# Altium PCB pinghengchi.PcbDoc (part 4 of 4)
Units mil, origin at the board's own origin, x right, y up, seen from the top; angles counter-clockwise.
Board outline 3880 x 3935 mil, 2 copper layers (Top Layer, Bottom Layer); 79 components, 147 nets, 520 pads, 52 vias.
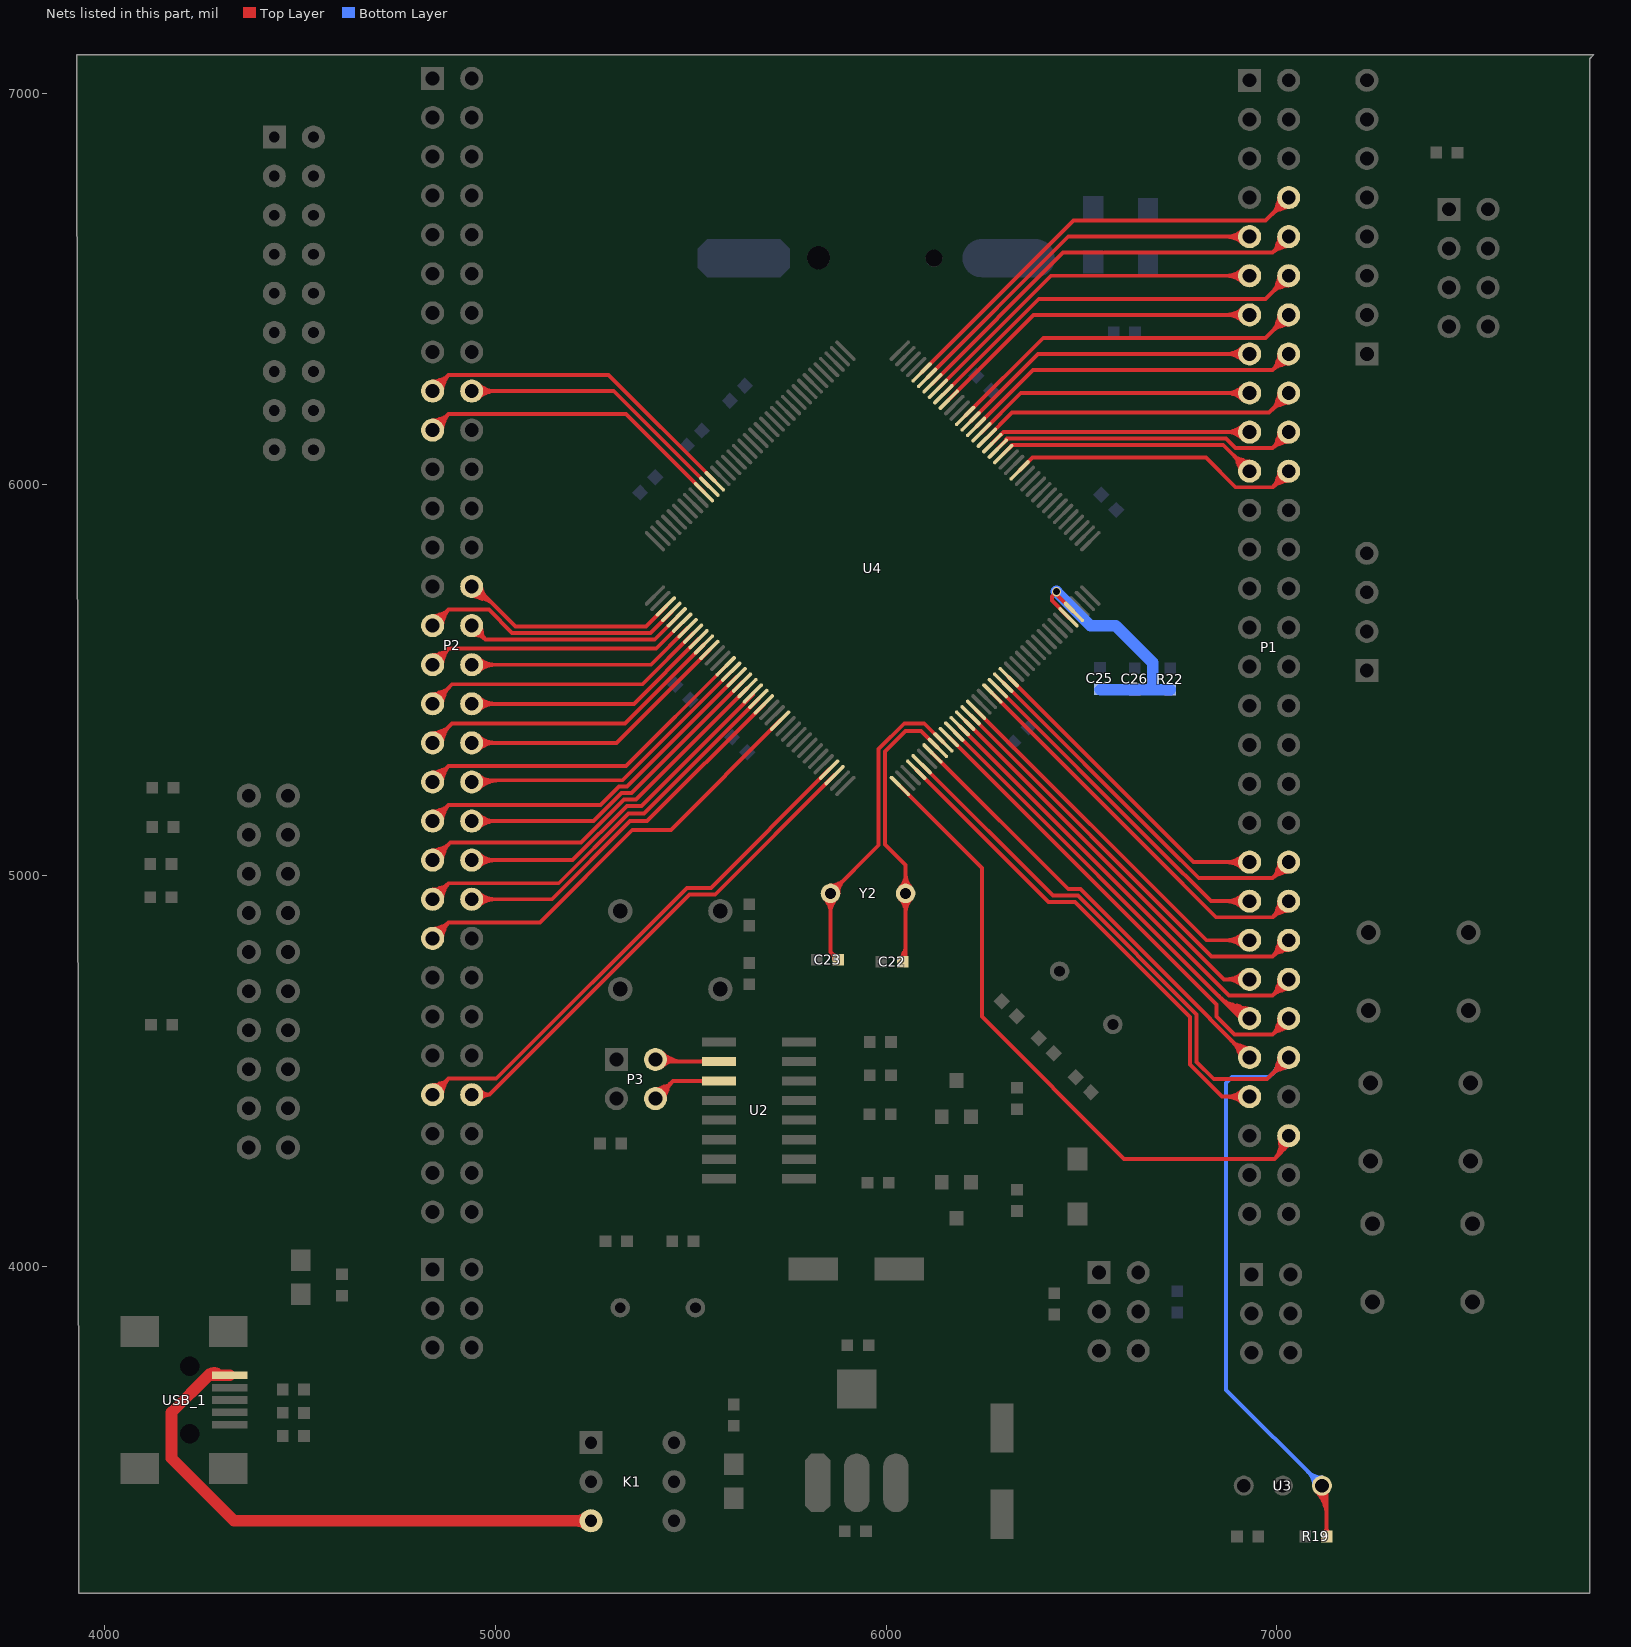
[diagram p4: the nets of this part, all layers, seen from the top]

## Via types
v1: diameter 24, hole 18, Top Layer to Bottom Layer, 42 vias
v2: diameter 24, hole 16, Top Layer to Bottom Layer, 4 vias
v3: diameter 125.98, hole 118.11, Top Layer to Bottom Layer, 4 vias
v4: diameter 30, hole 20, Top Layer to Bottom Layer, 2 vias

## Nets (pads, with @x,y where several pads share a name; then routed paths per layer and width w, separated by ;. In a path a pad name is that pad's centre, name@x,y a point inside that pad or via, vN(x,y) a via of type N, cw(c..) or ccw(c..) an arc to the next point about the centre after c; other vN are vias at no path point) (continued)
PC7: P2.17 U4.97 | length 1224.5
  Top Layer w10: P2.17@4834.67,6241.26 cw(c4872.93,6232.2) 4863.31,6270.32 ; P2.17@4840,6240 4881.03,6281.03 ; P2.17@4841.26,6234.67 ccw(c4832.2,6272.93) 4870.32,6263.31 ; U4.97@5561.97,6009.22 5290.17,6281.03 4881.03,6281.03 ; 4864.3,6264.3 ccw(c4887.9,6240.7) 4854.53,6240.21 cw(c4887.9,6240.7) 4864.3,6264.3 ; 4864.3,6264.3 cw(c4840.7,6287.9) 4840.21,6254.53 ccw(c4840.7,6287.9) 4864.3,6264.3 ; 4881.03,6281.03 ccw(c4920.87,6241.18) 4864.52,6240.36 cw(c4920.87,6241.18) 4881.03,6281.03 ; 4881.03,6281.03 cw(c4841.18,6320.87) 4840.36,6264.52 ccw(c4841.18,6320.87) 4881.03,6281.03
PC8: P2.18 U4.98 | length 1005.6
  Top Layer w10: P2.18@4940,6240 5303.35,6240 U4.98@5548.05,5995.3 ; 4975.07,6240 ccw(c4975.07,6204.93) 4950.27,6229.73 cw(c4975.07,6204.93) 4975.07,6240 ; 4975.07,6240 cw(c4975.07,6275.07) 4950.27,6250.27 ccw(c4975.07,6275.07) 4975.07,6240 ; 4999.21,6240 ccw(c4999.21,6180.79) 4957.34,6222.66 cw(c4999.21,6180.79) 4999.21,6240 ; 4999.21,6240 cw(c4999.21,6299.21) 4957.34,6257.34 ccw(c4999.21,6299.21) 4999.21,6240
PC9: P2.19 U4.99 | length 1166.7
  Top Layer w10: P2.19@4834.67,6141.26 cw(c4872.93,6132.2) 4863.31,6170.32 ; P2.19@4840,6140 4881.03,6181.03 ; P2.19@4841.26,6134.67 ccw(c4832.2,6172.93) 4870.32,6163.31 ; U4.99@5534.14,5981.38 5334.49,6181.03 4881.03,6181.03 ; 4864.3,6164.3 ccw(c4887.9,6140.7) 4854.53,6140.21 cw(c4887.9,6140.7) 4864.3,6164.3 ; 4864.3,6164.3 cw(c4840.7,6187.9) 4840.21,6154.53 ccw(c4840.7,6187.9) 4864.3,6164.3 ; 4881.03,6181.03 ccw(c4920.87,6141.18) 4864.52,6140.36 cw(c4920.87,6141.18) 4881.03,6181.03 ; 4881.03,6181.03 cw(c4841.18,6220.87) 4840.36,6164.52 ccw(c4841.18,6220.87) 4881.03,6181.03
PC10: P2.28 U4.111 | length 1013.3
  Top Layer w10: P2.28@4934.82,5738.23 ccw(c4978.99,5753.36) 4966.91,5708.26 ; P2.28@4940,5740 4950,5740 5052,5638 5385.63,5638 U4.111@5436.7,5689.07 ; P2.28@4940.22,5745.47 cw(c4938.95,5714.08) 4969.29,5722.21 ; P2.28@4944.28,5741.47 ccw(c5000.4,5760.7) 4985.04,5703.4 ; P2.28@4944.48,5740.66 ccw(c4970.46,5744.5) 4963.67,5719.13 ; P2.28@4940,5715.47 cw(c4940,5632.12) 4998.94,5691.06 ccw(c4940,5632.12) P2.28@4940,5715.47 ; P2.28@4940,5725.47 cw(c4940,5666.26) 4981.87,5708.13 ccw(c4940,5666.26) P2.28@4940,5725.47 ; P2.28@4964.53,5740 ccw(c4999.6,5740) 4974.8,5715.2 cw(c4999.6,5740) P2.28@4964.53,5740
PC11: P2.29 U4.112 | length 1047.4
  Top Layer w10: P2.29@4834.67,5641.26 cw(c4872.93,5632.2) 4863.31,5670.32 ; P2.29@4840,5640 4881.03,5681.03 ; P2.29@4841.26,5634.67 ccw(c4832.2,5672.93) 4870.32,5663.31 ; U4.112@5450.62,5675.15 5396.96,5621.5 5043.5,5621.5 4983.97,5681.03 4881.03,5681.03 ; 4864.3,5664.3 ccw(c4887.9,5640.7) 4854.53,5640.21 cw(c4887.9,5640.7) 4864.3,5664.3 ; 4864.3,5664.3 cw(c4840.7,5687.9) 4840.21,5654.53 ccw(c4840.7,5687.9) 4864.3,5664.3 ; 4881.03,5681.03 ccw(c4920.87,5641.18) 4864.52,5640.36 cw(c4920.87,5641.18) 4881.03,5681.03 ; 4881.03,5681.03 cw(c4841.18,5720.87) 4840.36,5664.52 ccw(c4841.18,5720.87) 4881.03,5681.03
PC12: P2.30 U4.113 | length 769.4
  Top Layer w10: P2.30@4927.76,5630.53 ccw(c4962.2,5657.17) 4956.68,5613.99 ; P2.30@4940,5640 4975,5605 ; P2.30@4949.47,5652.24 cw(c4922.83,5617.8) 4966.01,5623.32 ; U4.113@5464.54,5661.23 5408.3,5605 4975,5605 ; 4975,5605 ccw(c4948.36,5578.36) 4943.3,5615.69 cw(c4948.36,5578.36) 4975,5605 ; 4975,5605 cw(c5001.64,5631.64) 4964.31,5636.7 ccw(c5001.64,5631.64) 4975,5605
PC13: P1.51 U4.7 | length 1473.5
  Top Layer w10: U4.7@6118.75,5313.25 6466,4966 6497.34,4966 6828.5,4634.84 6828.5,4633.17 6926.67,4535 P1.51@6930,4535 ; 6899.89,4555.83 ccw(c6934.63,4565.13) P1.51@6929.17,4529.59 ; 6906.13,4565.92 cw(c6895.51,4526.27) P1.51@6935.31,4536.34 ; 6882.44,4579.23 ccw(c6930,4626.79) 6930,4559.53 cw(c6930,4626.79) 6882.44,4579.23 ; 6890.49,4571.18 cw(c6854.31,4535) 6905.47,4535 ccw(c6854.31,4535) 6890.49,4571.18 ; 6899.51,4562.16 ccw(c6930,4592.65) 6930,4549.53 cw(c6930,4592.65) 6899.51,4562.16
PC14: C22.2 U4.8 Y2.1 | length 1177.4
  Top Layer w10: 6045.52,4804.48 ccw(c6056.78,4797.97) C22.2@6048.71,4787.78 ; U4.8@6132.67,5327.17 6089.84,5370 6049.77,5370 5997.59,5317.83 5997.59,5080.41 6050,5028 Y2.1@6050,4955 6050,4787.44 C22.2@6042.5,4779.94 ; C22.2@6042.5,4779.94 ccw(c6024.39,4798.04) 6050,4798.04 cw(c6024.39,4798.04) C22.2@6042.5,4779.94 ; 6050,4906.72 ccw(c6001.72,4906.72) 6035.86,4940.86 cw(c6001.72,4906.72) 6050,4906.72 ; 6050,4906.72 cw(c6098.28,4906.72) 6064.14,4940.86 ccw(c6098.28,4906.72) 6050,4906.72 ; 6050,5003.28 ccw(c6098.28,5003.28) 6064.14,4969.14 cw(c6098.28,5003.28) 6050,5003.28 ; 6050,5003.28 cw(c6001.72,5003.28) 6035.86,4969.14 ccw(c6001.72,5003.28) 6050,5003.28 ; C22.2@6035.43,4787.01 ccw(c6000.25,4822.18) 6050,4822.18 cw(c6000.25,4822.18) C22.2@6035.43,4787.01
PC15: C23.2 U4.9 Y2.2 | length 1268.3
  Top Layer w10: C23.2@5877.5,4784.94 5857.87,4804.56 Y2.2@5857.87,4955 ; 5883.07,4981.75 ccw(c5892.12,4947.99) Y2.2@5857.87,4955 ; 5884.63,4980.2 cw(c5850.86,4989.24) Y2.2@5857.87,4955 ; U4.9@6146.59,5341.09 6097.68,5390 6046.43,5390 5981.09,5324.66 5981.09,5078.22 Y2.2@5857.87,4955 ; 5857.87,4906.72 ccw(c5809.59,4906.72) 5843.73,4940.86 cw(c5809.59,4906.72) 5857.87,4906.72 ; 5857.87,4906.72 cw(c5906.16,4906.72) 5872.02,4940.86 ccw(c5906.16,4906.72) 5857.87,4906.72 ; 5860.43,4802.01 ccw(c5877.5,4819.08) 5877.5,4794.94 cw(c5877.5,4819.08) 5860.43,4802.01 ; 5860.43,4802.01 cw(c5843.36,4784.94) 5867.5,4784.94 ccw(c5843.36,4784.94) 5860.43,4802.01 ; 5892.02,4989.14 ccw(c5926.16,4955) 5877.87,4955 cw(c5926.16,4955) 5892.02,4989.14 ; 5892.02,4989.14 cw(c5857.87,5023.28) 5857.87,4975 ccw(c5857.87,5023.28) 5892.02,4989.14
PD0: P2.31 U4.114 | length 1055.8
  Top Layer w10: P2.31@4834.67,5541.26 cw(c4872.93,5532.2) 4863.31,5570.32 ; P2.31@4840,5540 4881.03,5581.03 ; P2.31@4841.26,5534.67 ccw(c4832.2,5572.93) 4870.32,5563.31 ; U4.114@5478.46,5647.31 5412.17,5581.03 4881.03,5581.03 ; 4864.3,5564.3 ccw(c4887.9,5540.7) 4854.53,5540.21 cw(c4887.9,5540.7) 4864.3,5564.3 ; 4864.3,5564.3 cw(c4840.7,5587.9) 4840.21,5554.53 ccw(c4840.7,5587.9) 4864.3,5564.3 ; 4881.03,5581.03 ccw(c4920.87,5541.18) 4864.52,5540.36 cw(c4920.87,5541.18) 4881.03,5581.03 ; 4881.03,5581.03 cw(c4841.18,5620.87) 4840.36,5564.52 ccw(c4841.18,5620.87) 4881.03,5581.03
PD1: P2.32 U4.115 | length 887.3
  Top Layer w10: P2.32@4940,5540 5398.98,5540 U4.115@5492.38,5633.4 ; 4975.07,5540 ccw(c4975.07,5504.93) 4950.27,5529.73 cw(c4975.07,5504.93) 4975.07,5540 ; 4975.07,5540 cw(c4975.07,5575.07) 4950.27,5550.27 ccw(c4975.07,5575.07) 4975.07,5540 ; 4999.21,5540 ccw(c4999.21,5480.79) 4957.34,5522.66 cw(c4999.21,5480.79) 4999.21,5540 ; 4999.21,5540 cw(c4999.21,5599.21) 4957.34,5557.34 ccw(c4999.21,5599.21) 4999.21,5540
PD2: P2.33 U4.116 | length 1122
  Top Layer w10: P2.33@4834.64,5441.1 cw(c4872.3,5433.39) 4862.35,5470.52 ; P2.33@4840,5440 4890,5490 5376.82,5490 U4.116@5506.3,5619.48 ; P2.33@4841.1,5434.64 ccw(c4833.39,5472.3) 4870.52,5462.35 ; 4864.8,5464.8 ccw(c4889.6,5440) 4854.53,5440 cw(c4889.6,5440) 4864.8,5464.8 ; 4864.8,5464.8 cw(c4840,5489.6) 4840,5454.53 ccw(c4840,5489.6) 4864.8,5464.8 ; 4881.87,5481.87 ccw(c4923.74,5440) 4864.53,5440 cw(c4923.74,5440) 4881.87,5481.87 ; 4881.87,5481.87 cw(c4840,5523.74) 4840,5464.53 ccw(c4840,5523.74) 4881.87,5481.87
PD3: P2.34 U4.117 | length 945
  Top Layer w10: P2.34@4940,5440 5354.66,5440 U4.117@5520.22,5605.56 ; 4975.07,5440 ccw(c4975.07,5404.93) 4950.27,5429.73 cw(c4975.07,5404.93) 4975.07,5440 ; 4975.07,5440 cw(c4975.07,5475.07) 4950.27,5450.27 ccw(c4975.07,5475.07) 4975.07,5440 ; 4999.21,5440 ccw(c4999.21,5380.79) 4957.34,5422.66 cw(c4999.21,5380.79) 4999.21,5440 ; 4999.21,5440 cw(c4999.21,5499.21) 4957.34,5457.34 ccw(c4999.21,5499.21) 4999.21,5440
PD4: P2.35 U4.118 | length 1179.7
  Top Layer w10: P2.35@4834.64,5341.1 cw(c4872.3,5333.39) 4862.35,5370.52 ; P2.35@4840,5340 4890,5390 5332.5,5390 U4.118@5534.14,5591.64 ; P2.35@4841.1,5334.64 ccw(c4833.39,5372.3) 4870.52,5362.35 ; 4864.8,5364.8 ccw(c4889.6,5340) 4854.53,5340 cw(c4889.6,5340) 4864.8,5364.8 ; 4864.8,5364.8 cw(c4840,5389.6) 4840,5354.53 ccw(c4840,5389.6) 4864.8,5364.8 ; 4881.87,5381.87 ccw(c4923.74,5340) 4864.53,5340 cw(c4923.74,5340) 4881.87,5381.87 ; 4881.87,5381.87 cw(c4840,5423.74) 4840,5364.53 ccw(c4840,5423.74) 4881.87,5381.87
PD5: P2.36 U4.119 | length 1002.7
  Top Layer w10: P2.36@4940,5340 5310.34,5340 U4.119@5548.05,5577.72 ; 4975.07,5340 ccw(c4975.07,5304.93) 4950.27,5329.73 cw(c4975.07,5304.93) 4975.07,5340 ; 4975.07,5340 cw(c4975.07,5375.07) 4950.27,5350.27 ccw(c4975.07,5375.07) 4975.07,5340 ; 4999.21,5340 ccw(c4999.21,5280.79) 4957.34,5322.66 cw(c4999.21,5280.79) 4999.21,5340 ; 4999.21,5340 cw(c4999.21,5399.21) 4957.34,5357.34 ccw(c4999.21,5399.21) 4999.21,5340
PD6: P2.37 U4.122 | length 1245.3
  Top Layer w10: P2.37@4834.67,5241.26 cw(c4872.93,5232.2) 4863.31,5270.32 ; P2.37@4840,5240 4881.03,5281.03 ; P2.37@4841.26,5234.67 ccw(c4832.2,5272.93) 4870.32,5263.31 ; U4.122@5589.81,5535.96 5334.88,5281.03 4881.03,5281.03 ; 4864.3,5264.3 ccw(c4887.9,5240.7) 4854.53,5240.21 cw(c4887.9,5240.7) 4864.3,5264.3 ; 4864.3,5264.3 cw(c4840.7,5287.9) 4840.21,5254.53 ccw(c4840.7,5287.9) 4864.3,5264.3 ; 4881.03,5281.03 ccw(c4920.87,5241.18) 4864.52,5240.36 cw(c4920.87,5241.18) 4881.03,5281.03 ; 4881.03,5281.03 cw(c4841.18,5320.87) 4840.36,5264.52 ccw(c4841.18,5320.87) 4881.03,5281.03
PD7: P2.38 U4.123 | length 1045.8
  Top Layer w10: P2.38@4940,5240 4944.5,5244.5 5326.19,5244.5 U4.123@5603.73,5522.04 ; P2.38@4950.27,5229.73 cw(c4985.94,5194.06) 4985.94,5244.5 ccw(c4985.94,5194.06) P2.38@4950.27,5229.73 ; P2.38@4957.34,5222.66 cw(c5010.08,5169.92) 5010.08,5244.5 ccw(c5010.08,5169.92) P2.38@4957.34,5222.66 ; P2.38@4957.34,5257.34 ccw(c4988.35,5288.35) 4988.35,5244.5 cw(c4988.35,5288.35) P2.38@4957.34,5257.34
PE0: P2.53 U4.141 | length 1731.6
  Top Layer w10: P2.53@4834.67,4441.26 cw(c4872.93,4432.2) 4863.31,4470.32 ; P2.53@4840,4440 4881.03,4481.03 ; P2.53@4841.26,4434.67 ccw(c4832.2,4472.93) 4870.32,4463.31 ; U4.141@5854.28,5271.49 5551.79,4969 5490.67,4969 5002.69,4481.03 4881.03,4481.03 ; 4864.3,4464.3 ccw(c4887.9,4440.7) 4854.53,4440.21 cw(c4887.9,4440.7) 4864.3,4464.3 ; 4864.3,4464.3 cw(c4840.7,4487.9) 4840.21,4454.53 ccw(c4840.7,4487.9) 4864.3,4464.3 ; 4881.03,4481.03 ccw(c4920.87,4441.18) 4864.52,4440.36 cw(c4920.87,4441.18) 4881.03,4481.03 ; 4881.03,4481.03 cw(c4841.18,4520.87) 4840.36,4464.52 ccw(c4841.18,4520.87) 4881.03,4481.03
PE1: P2.54 U4.142 | length 1382.7
  Top Layer w10: P2.54@4940,4440 4985,4440 ; U4.142@5868.2,5257.57 5563.13,4952.5 5497.5,4952.5 4985,4440 ; 4985,4440 ccw(c4985,4410.99) 4960.61,4426.71 cw(c4985,4410.99) 4985,4440 ; 4985,4440 cw(c4985,4469.01) 4960.61,4453.29 ccw(c4985,4469.01) 4985,4440
PE2: P1.56 U4.1 | length 1963.4
  Top Layer w10: U4.1@6035.23,5229.73 6245,5019.97 6245,4640 6608.97,4276.03 6993.97,4276.03 ; 7007.19,4314.15 cw(c7050.69,4316.04) P1.56@7018.59,4345.46 ; P1.56@7030,4335 7030,4312.06 6993.97,4276.03 ; 6993.97,4276.03 ccw(c6957.76,4312.24) 7006.61,4327.63 cw(c6957.76,4312.24) 6993.97,4276.03 ; 7005.63,4287.68 ccw(c6975.49,4317.83) 7016.14,4330.63 cw(c6975.49,4317.83) 7005.63,4287.68 ; 7017.28,4299.34 ccw(c6993.22,4323.41) 7025.68,4333.64 cw(c6993.22,4323.41) 7017.28,4299.34
PE5: P1.53 U4.4 | length 1567.1
  Top Layer w10: U4.4@6076.99,5271.49 6415.48,4933 6483.67,4933 6778,4638.67 6778,4516.83 6859.83,4435 P1.53@6930,4435 ; 6870.79,4435 ccw(c6870.79,4494.21) 6912.66,4452.34 cw(c6870.79,4494.21) 6870.79,4435 ; 6870.79,4435 cw(c6870.79,4375.79) 6912.66,4417.66 ccw(c6870.79,4375.79) 6870.79,4435 ; 6894.93,4435 ccw(c6894.93,4470.07) 6919.73,4445.27 cw(c6894.93,4470.07) 6894.93,4435 ; 6894.93,4435 cw(c6894.93,4399.93) 6919.73,4424.73 ccw(c6894.93,4399.93) 6894.93,4435
PE6: P1.52 R19.1 U3.1 U4.5 | length 4071.6
  Top Layer w10: U4.5@6090.91,5285.41 6426.82,4949.5 6490.5,4949.5 6794.5,4645.5 6794.5,4523.67 6838.17,4480 6975,4480 P1.52@7030,4535 ; 6999.48,4512.65 cw(c7036.61,4502.7) P1.52@7028.9,4540.36 ; 7007.65,4504.48 ccw(c6997.7,4541.61) P1.52@7035.36,4533.9 ; U3.1@7109.67,3420.11 cw(c7105.84,3405.83) 7118.65,3413.22 ; U3.1@7115,3440 7127,3428 R19.1@7127,3310 ; 7121.78,3407.8 cw(c7131.04,3413.14) U3.1@7125.56,3422.32 ; 6988.13,4493.13 ccw(c6946.26,4535) 7005.47,4535 cw(c6946.26,4535) 6988.13,4493.13 ; 6988.13,4493.13 cw(c7030,4451.26) 7030,4510.47 ccw(c7030,4451.26) 6988.13,4493.13 ; 7005.2,4510.2 ccw(c6980.4,4535) 7015.47,4535 cw(c6980.4,4535) 7005.2,4510.2 ; 7005.2,4510.2 cw(c7030,4485.4) 7030,4520.47 ccw(c7030,4485.4) 7005.2,4510.2 ; 7127,3334.14 ccw(c7151.14,3334.14) 7134.07,3317.07 cw(c7151.14,3334.14) 7127,3334.14 ; 7127,3334.14 cw(c7102.86,3334.14) 7119.93,3317.07 ccw(c7102.86,3334.14) 7127,3334.14 ; U3.1@7100.44,3425.44 cw(c7036.32,3361.32) 7127,3361.32 ccw(c7036.32,3361.32) U3.1@7100.44,3425.44 ; U3.1@7107.51,3432.51 cw(c7060.46,3385.46) 7127,3385.46 ccw(c7060.46,3385.46) U3.1@7107.51,3432.51 ; U3.1@7114.58,3439.58 cw(c7084.6,3409.6) 7127,3409.6 ccw(c7084.6,3409.6) U3.1@7114.58,3439.58
  Bottom Layer w10: P1.52@7030,4535 6980,4485 6885,4485 6870,4470 6870,3685 U3.1@7115,3440 ; 6988.13,4493.13 ccw(c6946.26,4535) 7005.47,4535 cw(c6946.26,4535) 6988.13,4493.13 ; 6988.13,4493.13 cw(c7030,4451.26) 7030,4510.47 ccw(c7030,4451.26) 6988.13,4493.13 ; 7005.2,4510.2 ccw(c6980.4,4535) 7015.47,4535 cw(c6980.4,4535) 7005.2,4510.2 ; 7005.2,4510.2 cw(c7030,4485.4) 7030,4520.47 ccw(c7030,4485.4) 7005.2,4510.2 ; 7079.85,3475.15 ccw(c7115,3510.3) 7115,3460.59 cw(c7115,3510.3) 7079.85,3475.15 ; 7079.85,3475.15 cw(c7044.7,3440) 7094.41,3440 ccw(c7044.7,3440) 7079.85,3475.15
PE7: P1.16 U4.58 | length 1250.1
  Top Layer w10: U4.58@6230.11,6148.41 6375.66,6293.97 6988.97,6293.97 ; 6999.68,6311.69 cw(c7037.8,6302.07) P1.16@7028.74,6340.33 ; 7006.69,6304.68 ccw(c6997.07,6342.8) P1.16@7035.33,6333.74 ; P1.16@7030,6335 6988.97,6293.97 ; 6988.97,6293.97 ccw(c6949.13,6333.82) 7005.48,6334.64 cw(c6949.13,6333.82) 6988.97,6293.97 ; 6988.97,6293.97 cw(c7028.82,6254.13) 7029.64,6310.48 ccw(c7028.82,6254.13) 6988.97,6293.97 ; 7005.7,6310.7 ccw(c6982.1,6334.3) 7015.47,6334.79 cw(c6982.1,6334.3) 7005.7,6310.7 ; 7005.7,6310.7 cw(c7029.3,6287.1) 7029.79,6320.47 ccw(c7029.3,6287.1) 7005.7,6310.7
PE8: P1.15 U4.59 | length 1081.5
  Top Layer w10: U4.59@6216.19,6162.33 6388.85,6335 P1.15@6930,6335 ; 6870.79,6335 ccw(c6870.79,6394.21) 6912.66,6352.34 cw(c6870.79,6394.21) 6870.79,6335 ; 6870.79,6335 cw(c6870.79,6275.79) 6912.66,6317.66 ccw(c6870.79,6275.79) 6870.79,6335 ; 6894.93,6335 ccw(c6894.93,6370.07) 6919.73,6345.27 cw(c6894.93,6370.07) 6894.93,6335 ; 6894.93,6335 cw(c6894.93,6299.93) 6919.73,6324.73 ccw(c6894.93,6299.93) 6894.93,6335
PE9: P1.14 U4.60 | length 1316.2
  Top Layer w10: U4.60@6202.27,6176.25 6402.04,6376.03 6971.03,6376.03 P1.14@7030,6435 ; 6999.48,6412.65 cw(c7036.61,6402.7) P1.14@7028.9,6440.36 ; 7007.65,6404.48 ccw(c6997.7,6441.61) P1.14@7035.36,6433.9 ; 6988.13,6393.13 ccw(c6946.26,6435) 7005.47,6435 cw(c6946.26,6435) 6988.13,6393.13 ; 6988.13,6393.13 cw(c7030,6351.26) 7030,6410.47 ccw(c7030,6351.26) 6988.13,6393.13 ; 7005.2,6410.2 ccw(c6980.4,6435) 7015.47,6435 cw(c6980.4,6435) 7005.2,6410.2 ; 7005.2,6410.2 cw(c7030,6385.4) 7030,6420.47 ccw(c7030,6385.4) 7005.2,6410.2
PE10: P1.13 U4.63 | length 1155.6
  Top Layer w10: U4.63@6160.51,6218.01 6377.5,6435 P1.13@6930,6435 ; 6870.79,6435 ccw(c6870.79,6494.21) 6912.66,6452.34 cw(c6870.79,6494.21) 6870.79,6435 ; 6870.79,6435 cw(c6870.79,6375.79) 6912.66,6417.66 ccw(c6870.79,6375.79) 6870.79,6435 ; 6894.93,6435 ccw(c6894.93,6470.07) 6919.73,6445.27 cw(c6894.93,6470.07) 6894.93,6435 ; 6894.93,6435 cw(c6894.93,6399.93) 6919.73,6424.73 ccw(c6894.93,6399.93) 6894.93,6435
PE11: P1.12 U4.64 | length 1390.3
  Top Layer w10: U4.64@6146.59,6231.93 6390.69,6476.03 6971.03,6476.03 P1.12@7030,6535 ; 6999.48,6512.65 cw(c7036.61,6502.7) P1.12@7028.9,6540.36 ; 7007.65,6504.48 ccw(c6997.7,6541.61) P1.12@7035.36,6533.9 ; 6988.13,6493.13 ccw(c6946.26,6535) 7005.47,6535 cw(c6946.26,6535) 6988.13,6493.13 ; 6988.13,6493.13 cw(c7030,6451.26) 7030,6510.47 ccw(c7030,6451.26) 6988.13,6493.13 ; 7005.2,6510.2 ccw(c6980.4,6535) 7015.47,6535 cw(c6980.4,6535) 7005.2,6510.2 ; 7005.2,6510.2 cw(c7030,6485.4) 7030,6520.47 ccw(c7030,6485.4) 7005.2,6510.2
PE12: P1.11 U4.65 | length 1213.3
  Top Layer w10: U4.65@6132.67,6245.85 6421.82,6535 P1.11@6930,6535 ; 6870.79,6535 ccw(c6870.79,6594.21) 6912.66,6552.34 cw(c6870.79,6594.21) 6870.79,6535 ; 6870.79,6535 cw(c6870.79,6475.79) 6912.66,6517.66 ccw(c6870.79,6475.79) 6870.79,6535 ; 6894.93,6535 ccw(c6894.93,6570.07) 6919.73,6545.27 cw(c6894.93,6570.07) 6894.93,6535 ; 6894.93,6535 cw(c6894.93,6499.93) 6919.73,6524.73 ccw(c6894.93,6499.93) 6894.93,6535
PE13: P1.10 U4.66 | length 1439.6
  Top Layer w10: U4.66@6118.75,6259.77 6452.95,6593.97 6988.97,6593.97 ; 6999.68,6611.69 cw(c7037.8,6602.07) P1.10@7028.74,6640.33 ; 7006.69,6604.68 ccw(c6997.07,6642.8) P1.10@7035.33,6633.74 ; P1.10@7030,6635 6988.97,6593.97 ; 6988.97,6593.97 ccw(c6949.13,6633.82) 7005.48,6634.64 cw(c6949.13,6633.82) 6988.97,6593.97 ; 6988.97,6593.97 cw(c7028.82,6554.13) 7029.64,6610.48 ccw(c7028.82,6554.13) 6988.97,6593.97 ; 7005.7,6610.7 ccw(c6982.1,6634.3) 7015.47,6634.79 cw(c6982.1,6634.3) 7005.7,6610.7 ; 7005.7,6610.7 cw(c7029.3,6587.1) 7029.79,6620.47 ccw(c7029.3,6587.1) 7005.7,6610.7
PE14: P1.9 U4.67 | length 1271
  Top Layer w10: U4.67@6104.83,6273.69 6466.14,6635 P1.9@6930,6635 ; 6870.79,6635 ccw(c6870.79,6694.21) 6912.66,6652.34 cw(c6870.79,6694.21) 6870.79,6635 ; 6870.79,6635 cw(c6870.79,6575.79) 6912.66,6617.66 ccw(c6870.79,6575.79) 6870.79,6635 ; 6894.93,6635 ccw(c6894.93,6670.07) 6919.73,6645.27 cw(c6894.93,6670.07) 6894.93,6635 ; 6894.93,6635 cw(c6894.93,6599.93) 6919.73,6624.73 ccw(c6894.93,6599.93) 6894.93,6635
PE15: P1.8 U4.68 | length 1505.7
  Top Layer w10: U4.68@6090.91,6287.61 6479.33,6676.03 6971.03,6676.03 P1.8@7030,6735 ; 6999.48,6712.65 cw(c7036.61,6702.7) P1.8@7028.9,6740.36 ; 7007.65,6704.48 ccw(c6997.7,6741.61) P1.8@7035.36,6733.9 ; 6988.13,6693.13 ccw(c6946.26,6735) 7005.47,6735 cw(c6946.26,6735) 6988.13,6693.13 ; 6988.13,6693.13 cw(c7030,6651.26) 7030,6710.47 ccw(c7030,6651.26) 6988.13,6693.13 ; 7005.2,6710.2 ccw(c6980.4,6735) 7015.47,6735 cw(c6980.4,6735) 7005.2,6710.2 ; 7005.2,6710.2 cw(c7030,6685.4) 7030,6720.47 ccw(c7030,6685.4) 7005.2,6710.2
PF0: P1.50 U4.10 | length 1592.5
  Top Layer w10: U4.10@6160.51,5355.01 6845,4670.52 6845,4640 6891.03,4593.97 6988.97,4593.97 ; 6999.68,4611.69 cw(c7037.8,4602.07) P1.50@7028.74,4640.33 ; 7006.69,4604.68 ccw(c6997.07,4642.8) P1.50@7035.33,4633.74 ; P1.50@7030,4635 6988.97,4593.97 ; 6988.97,4593.97 ccw(c6949.13,4633.82) 7005.48,4634.64 cw(c6949.13,4633.82) 6988.97,4593.97 ; 6988.97,4593.97 cw(c7028.82,4554.13) 7029.64,4610.48 ccw(c7028.82,4554.13) 6988.97,4593.97 ; 7005.7,4610.7 ccw(c6982.1,4634.3) 7015.47,4634.79 cw(c6982.1,4634.3) 7005.7,4610.7 ; 7005.7,4610.7 cw(c7029.3,4587.1) 7029.79,4620.47 ccw(c7029.3,4587.1) 7005.7,4610.7
PF1: P1.49 U4.11 | length 1657.5
  Top Layer w10: U4.11@6174.43,5368.93 6908.35,4635 P1.49@6930,4635 ; 6876.73,4673.8 cw(c6856.91,4599.82) P1.49@6925.92,4633.04 ; 6897.78,4668.16 cw(c6882.81,4612.29) P1.49@6934.93,4637.37 ; 6899.57,4657.68 cw(c6889.67,4620.73) P1.49@6925.73,4633.49 ; 6918.83,4662.52 cw(c6908.71,4624.75) P1.49@6943.94,4641.71 ; 6851.18,4692.18 ccw(c6930,4771) 6930,4659.53 cw(c6930,4771) 6851.18,4692.18 ; 6868.25,4675.11 ccw(c6930,4736.86) 6930,4649.53 cw(c6930,4736.86) 6868.25,4675.11 ; 6885.32,4658.03 ccw(c6930,4702.72) 6930,4639.53 cw(c6930,4702.72) 6885.32,4658.03
PF2: P1.48 U4.12 | length 1516.9
  Top Layer w10: U4.12@6188.35,5382.85 6877.22,4693.97 6988.97,4693.97 ; 6999.68,4711.69 cw(c7037.8,4702.07) P1.48@7028.74,4740.33 ; 7006.69,4704.68 ccw(c6997.07,4742.8) P1.48@7035.33,4733.74 ; P1.48@7030,4735 6988.97,4693.97 ; 6988.97,4693.97 ccw(c6949.13,4733.82) 7005.48,4734.64 cw(c6949.13,4733.82) 6988.97,4693.97 ; 6988.97,4693.97 cw(c7028.82,4654.13) 7029.64,4710.48 ccw(c7028.82,4654.13) 6988.97,4693.97 ; 7005.7,4710.7 ccw(c6982.1,4734.3) 7015.47,4734.79 cw(c6982.1,4734.3) 7005.7,4710.7 ; 7005.7,4710.7 cw(c7029.3,4687.1) 7029.79,4720.47 ccw(c7029.3,4687.1) 7005.7,4710.7
PF3: P1.47 U4.13 | length 1298.1
  Top Layer w10: U4.13@6202.27,5396.77 6864.03,4735 P1.47@6930,4735 ; 6870.79,4735 ccw(c6870.79,4794.21) 6912.66,4752.34 cw(c6870.79,4794.21) 6870.79,4735 ; 6870.79,4735 cw(c6870.79,4675.79) 6912.66,4717.66 ccw(c6870.79,4675.79) 6870.79,4735 ; 6894.93,4735 ccw(c6894.93,4770.07) 6919.73,4745.27 cw(c6894.93,4770.07) 6894.93,4735 ; 6894.93,4735 cw(c6894.93,4699.93) 6919.73,4724.73 ccw(c6894.93,4699.93) 6894.93,4735
PF4: P1.46 U4.14 | length 1459.2
  Top Layer w10: U4.14@6216.19,5410.68 6832.9,4793.97 6988.97,4793.97 ; 6999.68,4811.69 cw(c7037.8,4802.07) P1.46@7028.74,4840.33 ; 7006.69,4804.68 ccw(c6997.07,4842.8) P1.46@7035.33,4833.74 ; P1.46@7030,4835 6988.97,4793.97 ; 6988.97,4793.97 ccw(c6949.13,4833.82) 7005.48,4834.64 cw(c6949.13,4833.82) 6988.97,4793.97 ; 6988.97,4793.97 cw(c7028.82,4754.13) 7029.64,4810.48 ccw(c7028.82,4754.13) 6988.97,4793.97 ; 7005.7,4810.7 ccw(c6982.1,4834.3) 7015.47,4834.79 cw(c6982.1,4834.3) 7005.7,4810.7 ; 7005.7,4810.7 cw(c7029.3,4787.1) 7029.79,4820.47 ccw(c7029.3,4787.1) 7005.7,4810.7
PF5: P1.45 U4.15 | length 1240.3
  Top Layer w10: U4.15@6230.11,5424.6 6819.71,4835 P1.45@6930,4835 ; 6870.79,4835 ccw(c6870.79,4894.21) 6912.66,4852.34 cw(c6870.79,4894.21) 6870.79,4835 ; 6870.79,4835 cw(c6870.79,4775.79) 6912.66,4817.66 ccw(c6870.79,4775.79) 6870.79,4835 ; 6894.93,4835 ccw(c6894.93,4870.07) 6919.73,4845.27 cw(c6894.93,4870.07) 6894.93,4835 ; 6894.93,4835 cw(c6894.93,4799.93) 6919.73,4824.73 ccw(c6894.93,4799.93) 6894.93,4835
PF6: P1.44 U4.18 | length 1385.1
  Top Layer w10: U4.18@6271.86,5466.36 6675,5063.23 6844.25,4893.97 6988.97,4893.97 ; 6999.68,4911.69 cw(c7037.8,4902.07) P1.44@7028.74,4940.33 ; 7006.69,4904.68 ccw(c6997.07,4942.8) P1.44@7035.33,4933.74 ; P1.44@7030,4935 6988.97,4893.97 ; 6988.97,4893.97 ccw(c6949.13,4933.82) 7005.48,4934.64 cw(c6949.13,4933.82) 6988.97,4893.97 ; 6988.97,4893.97 cw(c7028.82,4854.13) 7029.64,4910.48 ccw(c7028.82,4854.13) 6988.97,4893.97 ; 7005.7,4910.7 ccw(c6982.1,4934.3) 7015.47,4934.79 cw(c6982.1,4934.3) 7005.7,4910.7 ; 7005.7,4910.7 cw(c7029.3,4887.1) 7029.79,4920.47 ccw(c7029.3,4887.1) 7005.7,4910.7
PF7: P1.43 U4.19 | length 1166.3
  Top Layer w10: U4.19@6285.78,5480.28 6694.74,5071.32 6831.06,4935 P1.43@6930,4935 ; 6870.79,4935 ccw(c6870.79,4994.21) 6912.66,4952.34 cw(c6870.79,4994.21) 6870.79,4935 ; 6870.79,4935 cw(c6870.79,4875.79) 6912.66,4917.66 ccw(c6870.79,4875.79) 6870.79,4935 ; 6894.93,4935 ccw(c6894.93,4970.07) 6919.73,4945.27 cw(c6894.93,4970.07) 6894.93,4935 ; 6894.93,4935 cw(c6894.93,4899.93) 6919.73,4924.73 ccw(c6894.93,4899.93) 6894.93,4935
PF8: P1.42 U4.20 | length 1327.4
  Top Layer w10: U4.20@6299.7,5494.2 6711.24,5082.66 6799.93,4993.97 6988.97,4993.97 ; 6999.68,5011.69 cw(c7037.8,5002.07) P1.42@7028.74,5040.33 ; 7006.69,5004.68 ccw(c6997.07,5042.8) P1.42@7035.33,5033.74 ; P1.42@7030,5035 6988.97,4993.97 ; 6988.97,4993.97 ccw(c6949.13,5033.82) 7005.48,5034.64 cw(c6949.13,5033.82) 6988.97,4993.97 ; 6988.97,4993.97 cw(c7028.82,4954.13) 7029.64,5010.48 ccw(c7028.82,4954.13) 6988.97,4993.97 ; 7005.7,5010.7 ccw(c6982.1,5034.3) 7015.47,5034.79 cw(c6982.1,5034.3) 7005.7,5010.7 ; 7005.7,5010.7 cw(c7029.3,4987.1) 7029.79,5020.47 ccw(c7029.3,4987.1) 7005.7,5010.7
PF9: P1.41 U4.21 | length 1108.6
  Top Layer w10: U4.21@6313.62,5508.12 6727.74,5094 6786.74,5035 P1.41@6930,5035 ; 6870.79,5035 ccw(c6870.79,5094.21) 6912.66,5052.34 cw(c6870.79,5094.21) 6870.79,5035 ; 6870.79,5035 cw(c6870.79,4975.79) 6912.66,5017.66 ccw(c6870.79,4975.79) 6870.79,5035 ; 6894.93,5035 ccw(c6894.93,5070.07) 6919.73,5045.27 cw(c6894.93,5070.07) 6894.93,5035 ; 6894.93,5035 cw(c6894.93,4999.93) 6919.73,5024.73 ccw(c6894.93,4999.93) 6894.93,5035
PF12: P1.22 U4.50 | length 1123.6
  Top Layer w10: U4.50@6341.46,6037.06 6374.49,6070.08 6818.25,6070.08 6894.36,5993.97 6988.97,5993.97 ; 6999.68,6011.69 cw(c7037.8,6002.07) P1.22@7028.74,6040.33 ; 7006.69,6004.68 ccw(c6997.07,6042.8) P1.22@7035.33,6033.74 ; P1.22@7030,6035 6988.97,5993.97 ; 6988.97,5993.97 ccw(c6949.13,6033.82) 7005.48,6034.64 cw(c6949.13,6033.82) 6988.97,5993.97 ; 6988.97,5993.97 cw(c7028.82,5954.13) 7029.64,6010.48 ccw(c7028.82,5954.13) 6988.97,5993.97 ; 7005.7,6010.7 ccw(c6982.1,6034.3) 7015.47,6034.79 cw(c6982.1,6034.3) 7005.7,6010.7 ; 7005.7,6010.7 cw(c7029.3,5987.1) 7029.79,6020.47 ccw(c7029.3,5987.1) 7005.7,6010.7
PF13: P1.21 U4.53 | length 1061
  Top Layer w10: U4.53@6299.7,6078.82 6323.42,6102.54 6862.46,6102.54 P1.21@6930,6035 ; 6899.48,6057.35 ccw(c6936.61,6067.3) P1.21@6928.9,6029.64 ; 6907.65,6065.52 cw(c6897.7,6028.39) P1.21@6935.36,6036.1 ; 6888.13,6076.87 ccw(c6930,6118.74) 6930,6059.53 cw(c6930,6118.74) 6888.13,6076.87 ; 6888.13,6076.87 cw(c6846.26,6035) 6905.47,6035 ccw(c6846.26,6035) 6888.13,6076.87 ; 6905.2,6059.8 ccw(c6930,6084.6) 6930,6049.53 cw(c6930,6084.6) 6905.2,6059.8 ; 6905.2,6059.8 cw(c6880.4,6035) 6915.47,6035 ccw(c6880.4,6035) 6905.2,6059.8 ; U4.53@6320.92,6100.38 cw(c6326.12,6095.18) 6326.12,6102.54 ccw(c6326.12,6095.18) U4.53@6320.92,6100.38
PF14: P1.20 U4.54 | length 1196.5
  Top Layer w10: U4.54@6285.78,6092.74 6312.09,6119.04 ; 6999.68,6111.69 cw(c7037.8,6102.07) P1.20@7028.74,6140.33 ; 7006.69,6104.68 ccw(c6997.07,6142.8) P1.20@7035.33,6133.74 ; P1.20@7030,6135 6988.97,6093.97 ; 6312.09,6119.04 ccw(c6312.09,6113.87) 6306.92,6114.14 cw(c6312.09,6113.87) 6312.09,6119.04 ; 6312.09,6119.04 6869.3,6119.04 6894.36,6093.97 6988.97,6093.97 ; 6988.97,6093.97 ccw(c6949.13,6133.82) 7005.48,6134.64 cw(c6949.13,6133.82) 6988.97,6093.97 ; 6988.97,6093.97 cw(c7028.82,6054.13) 7029.64,6110.48 ccw(c7028.82,6054.13) 6988.97,6093.97 ; 7005.7,6110.7 ccw(c6982.1,6134.3) 7015.47,6134.79 cw(c6982.1,6134.3) 7005.7,6110.7 ; 7005.7,6110.7 cw(c7029.3,6087.1) 7029.79,6120.47 ccw(c7029.3,6087.1) 7005.7,6110.7 ; U4.54@6307,6114.3 cw(c6318.43,6102.87) 6318.43,6119.04 ccw(c6318.43,6102.87) U4.54@6307,6114.3
PF15: P1.19 U4.55 | length 966.5
  Top Layer w10: U4.55@6271.86,6106.66 6300.75,6135.54 6929.46,6135.54 P1.19@6930,6135 ; 6869.49,6135.54 cw(c6869.49,6074.49) 6912.66,6117.66 ccw(c6869.49,6074.49) 6869.49,6135.54 ; 6872.08,6135.54 ccw(c6872.08,6192.92) 6912.66,6152.34 cw(c6872.08,6192.92) 6872.08,6135.54 ; 6893.63,6135.54 cw(c6893.63,6098.63) 6919.73,6124.73 ccw(c6893.63,6098.63) 6893.63,6135.54 ; 6896.23,6135.54 ccw(c6896.23,6168.77) 6919.73,6145.27 cw(c6896.23,6168.77) 6896.23,6135.54
PG0: P1.18 U4.56 | length 1200.8
  Top Layer w10: U4.56@6257.94,6120.57 6322.37,6185 6980,6185 P1.18@7030,6235 ; 6999.48,6212.65 cw(c7036.61,6202.7) P1.18@7028.9,6240.36 ; 7007.65,6204.48 ccw(c6997.7,6241.61) P1.18@7035.36,6233.9 ; 6988.13,6193.13 ccw(c6946.26,6235) 7005.47,6235 cw(c6946.26,6235) 6988.13,6193.13 ; 6988.13,6193.13 cw(c7030,6151.26) 7030,6210.47 ccw(c7030,6151.26) 6988.13,6193.13 ; 7005.2,6210.2 ccw(c6980.4,6235) 7015.47,6235 cw(c6980.4,6235) 7005.2,6210.2 ; 7005.2,6210.2 cw(c7030,6185.4) 7030,6220.47 ccw(c7030,6185.4) 7005.2,6210.2
PG1: P1.17 U4.57 | length 1023.8
  Top Layer w10: U4.57@6244.02,6134.49 6344.53,6235 P1.17@6930,6235 ; 6870.79,6235 ccw(c6870.79,6294.21) 6912.66,6252.34 cw(c6870.79,6294.21) 6870.79,6235 ; 6870.79,6235 cw(c6870.79,6175.79) 6912.66,6217.66 ccw(c6870.79,6175.79) 6870.79,6235 ; 6894.93,6235 ccw(c6894.93,6270.07) 6919.73,6245.27 cw(c6894.93,6270.07) 6894.93,6235 ; 6894.93,6235 cw(c6894.93,6199.93) 6919.73,6224.73 ccw(c6894.93,6199.93) 6894.93,6235
PG9: P2.39 U4.124 | length 1303
  Top Layer w10: P2.39@4834.67,5141.26 cw(c4872.93,5132.2) 4863.31,5170.32 ; P2.39@4840,5140 4881.03,5181.03 ; P2.39@4841.26,5134.67 ccw(c4832.2,5172.93) 4870.32,5163.31 ; U4.124@5617.65,5508.12 5337.53,5228 5316.33,5228 5269.36,5181.03 4881.03,5181.03 ; 4864.3,5164.3 ccw(c4887.9,5140.7) 4854.53,5140.21 cw(c4887.9,5140.7) 4864.3,5164.3 ; 4864.3,5164.3 cw(c4840.7,5187.9) 4840.21,5154.53 ccw(c4840.7,5187.9) 4864.3,5164.3 ; 4881.03,5181.03 ccw(c4920.87,5141.18) 4864.52,5140.36 cw(c4920.87,5141.18) 4881.03,5181.03 ; 4881.03,5181.03 cw(c4841.18,5220.87) 4840.36,5164.52 ccw(c4841.18,5220.87) 4881.03,5181.03
PG10: P2.40 U4.125 | length 1134.5
  Top Layer w10: P2.40@4940,5140 5251.66,5140 5323.16,5211.5 5348.87,5211.5 U4.125@5631.57,5494.2 ; 4975.07,5140 ccw(c4975.07,5104.93) 4950.27,5129.73 cw(c4975.07,5104.93) 4975.07,5140 ; 4975.07,5140 cw(c4975.07,5175.07) 4950.27,5150.27 ccw(c4975.07,5175.07) 4975.07,5140 ; 4999.21,5140 ccw(c4999.21,5080.79) 4957.34,5122.66 cw(c4999.21,5080.79) 4999.21,5140 ; 4999.21,5140 cw(c4999.21,5199.21) 4957.34,5157.34 ccw(c4999.21,5199.21) 4999.21,5140
PG11: P2.41 U4.126 | length 1369.2
  Top Layer w10: P2.41@4834.64,5041.1 cw(c4872.3,5033.39) 4862.35,5070.52 ; P2.41@4840,5040 4885,5085 5220,5085 5330,5195 5360.21,5195 U4.126@5645.49,5480.28 ; P2.41@4841.1,5034.64 ccw(c4833.39,5072.3) 4870.52,5062.35 ; 4864.8,5064.8 ccw(c4889.6,5040) 4854.53,5040 cw(c4889.6,5040) 4864.8,5064.8 ; 4864.8,5064.8 cw(c4840,5089.6) 4840,5054.53 ccw(c4840,5089.6) 4864.8,5064.8 ; 4881.87,5081.87 ccw(c4923.74,5040) 4864.53,5040 cw(c4923.74,5040) 4881.87,5081.87 ; 4881.87,5081.87 cw(c4840,5123.74) 4840,5064.53 ccw(c4840,5123.74) 4881.87,5081.87
PG12: P2.42 U4.127 | length 1193.8
  Top Layer w10: P2.42@4940,5040 5198.33,5040 5336.83,5178.5 5374.22,5178.5 5659.41,5463.69 U4.127@5659.41,5466.36 ; 4975.07,5040 ccw(c4975.07,5004.93) 4950.27,5029.73 cw(c4975.07,5004.93) 4975.07,5040 ; 4975.07,5040 cw(c4975.07,5075.07) 4950.27,5050.27 ccw(c4975.07,5075.07) 4975.07,5040 ; 4999.21,5040 ccw(c4999.21,4980.79) 4957.34,5022.66 cw(c4999.21,4980.79) 4999.21,5040 ; 4999.21,5040 cw(c4999.21,5099.21) 4957.34,5057.34 ccw(c4999.21,5099.21) 4999.21,5040
PG13: P2.43 U4.128 | length 1418.5
  Top Layer w10: P2.43@4834.67,4941.26 cw(c4872.93,4932.2) 4863.31,4970.32 ; P2.43@4840,4940 4881.03,4981.03 ; P2.43@4841.26,4934.67 ccw(c4832.2,4972.93) 4870.32,4963.31 ; U4.128@5673.33,5452.44 5453.66,5232.78 5380.44,5159.56 5341.22,5159.56 5162.69,4981.03 4881.03,4981.03 ; 4864.3,4964.3 ccw(c4887.9,4940.7) 4854.53,4940.21 cw(c4887.9,4940.7) 4864.3,4964.3 ; 4864.3,4964.3 cw(c4840.7,4987.9) 4840.21,4954.53 ccw(c4840.7,4987.9) 4864.3,4964.3 ; 4881.03,4981.03 ccw(c4920.87,4941.18) 4864.52,4940.36 cw(c4920.87,4941.18) 4881.03,4981.03 ; 4881.03,4981.03 cw(c4841.18,5020.87) 4840.36,4964.52 ccw(c4841.18,5020.87) 4881.03,4981.03
PG14: P2.44 U4.129 | length 1250
  Top Layer w10: P2.44@4940,4940 5145,4940 5345,5140 5388.72,5140 U4.129@5687.25,5438.52 ; 4975.07,4940 ccw(c4975.07,4904.93) 4950.27,4929.73 cw(c4975.07,4904.93) 4975.07,4940 ; 4975.07,4940 cw(c4975.07,4975.07) 4950.27,4950.27 ccw(c4975.07,4975.07) 4975.07,4940 ; 4999.21,4940 ccw(c4999.21,4880.79) 4957.34,4922.66 cw(c4999.21,4880.79) 4999.21,4940 ; 4999.21,4940 cw(c4999.21,4999.21) 4957.34,4957.34 ccw(c4999.21,4999.21) 4999.21,4940
PG15: P2.45 U4.132 | length 1492.5
  Top Layer w10: P2.45@4834.67,4841.26 cw(c4872.93,4832.2) 4863.31,4870.32 ; P2.45@4840,4840 4881.03,4881.03 ; P2.45@4841.26,4834.67 ccw(c4832.2,4872.93) 4870.32,4863.31 ; U4.132@5729.01,5396.77 5449.74,5117.5 5350.72,5117.5 5114.25,4881.03 4881.03,4881.03 ; 4864.3,4864.3 ccw(c4887.9,4840.7) 4854.53,4840.21 cw(c4887.9,4840.7) 4864.3,4864.3 ; 4864.3,4864.3 cw(c4840.7,4887.9) 4840.21,4854.53 ccw(c4840.7,4887.9) 4864.3,4864.3 ; 4881.03,4881.03 ccw(c4920.87,4841.18) 4864.52,4840.36 cw(c4920.87,4841.18) 4881.03,4881.03 ; 4881.03,4881.03 cw(c4841.18,4920.87) 4840.36,4864.52 ccw(c4841.18,4920.87) 4881.03,4881.03
RXD: P3.4 U2.3 | length 614.3
  Top Layer w10: P3.4@5404.64,4431.1 cw(c5442.3,4423.39) 5432.35,4460.52 ; P3.4@5410,4430 5455,4475 U2.3@5572.64,4475 ; P3.4@5411.1,4424.64 ccw(c5403.39,4462.3) 5440.52,4452.35 ; 5434.8,4454.8 ccw(c5459.6,4430) 5424.53,4430 cw(c5459.6,4430) 5434.8,4454.8 ; 5434.8,4454.8 cw(c5410,4479.6) 5410,4444.53 ccw(c5410,4479.6) 5434.8,4454.8 ; 5451.87,4471.87 ccw(c5493.74,4430) 5434.53,4430 cw(c5493.74,4430) 5451.87,4471.87 ; 5451.87,4471.87 cw(c5410,4513.74) 5410,4454.53 ccw(c5410,4513.74) 5451.87,4471.87 ; 5524.7,4475 ccw(c5524.7,4491.44) 5536.33,4479.82 cw(c5524.7,4491.44) 5524.7,4475 ; 5524.7,4475 cw(c5524.7,4458.56) 5536.33,4470.18 ccw(c5524.7,4458.56) 5524.7,4475
TXD: P3.2 U2.2 | length 484.3
  Top Layer w10: P3.2@5410,4530 5415,4525 U2.2@5572.64,4525 ; 5457.14,4525 ccw(c5457.14,4482.86) 5427.34,4512.66 cw(c5457.14,4482.86) 5457.14,4525 ; 5457.14,4525 cw(c5457.14,4577.14) 5420.27,4540.27 ccw(c5457.14,4577.14) 5457.14,4525 ; 5524.7,4525 ccw(c5524.7,4541.44) 5536.33,4529.82 cw(c5524.7,4541.44) 5524.7,4525 ; 5524.7,4525 cw(c5524.7,4508.56) 5536.33,4520.18 ccw(c5524.7,4508.56) 5524.7,4525 ; P3.2@5427.34,4547.34 ccw(c5481.29,4601.29) 5481.29,4525 cw(c5481.29,4601.29) P3.2@5427.34,4547.34
"USB VCC": K1.3 USB_1.1 | length 1649.5
  Top Layer w30: USB_1.1@4321.06,3721.99 4267.03,3721.99 ; K1.3@5245,3350 4331.93,3350 4172,3509.93 4172,3626.97 4267.03,3721.99 ; 4267.03,3721.99 cw(c4281.15,3707.87) 4287.18,3726.91 ccw(c4281.15,3707.87) 4267.03,3721.99 ; 5209.93,3350 ccw(c5209.93,3385.07) 5234.73,3360.27 cw(c5209.93,3385.07) 5209.93,3350 ; 5209.93,3350 cw(c5209.93,3314.93) 5234.73,3339.73 ccw(c5209.93,3314.93) 5209.93,3350 ; 4262.68,3717.65 cw(c4285.62,3694.7) 4285.62,3727.15 ccw(c4285.62,3694.7) 4262.68,3717.65
VDDA: C25.2 C26.2 R22.1 U4.32 U4.33 | length 727.8
  Top Layer w10: U4.32@6466.74,5661.23 6424,5703.97 6424,5715 v1(6436,5727) 6436,5719.81 U4.33@6480.65,5675.15
  Bottom Layer w30: v1(6436,5727) 6523,5640 6587.41,5640 6682,5545.41 6682,5476 ; C25.2@6548.56,5476 6682,5476 ; R22.1@6727,5476 6682,5476
pads on no net: BAT.0 JTAG.11 JTAG.17 JTAG.19 K1.1 K1.4 K1.5 K1.6 P1.1 U2.9 U2.10 U2.11 U2.12 U2.15 U4.106 USB_1.4 USB_1.6 USB_1.7 USB_1.8 USB_1.9 USB_1.MH1 USB_1.MH2
copper on no net:
  other v3: 7605,3310 4100,3325 7625,6960 4095,6965

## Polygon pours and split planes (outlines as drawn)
GND on Bottom Layer "Top Layer-No Net" (solid, remove dead copper, pour order 3): 7720,3230 7720,7049.01 7684.98,7084 7596.93,7084 4062.04,7084 4057.04,7089 3980,7012.02 3980,3300.98 3984,3296.98 4061.04,3220 4142.09,3220

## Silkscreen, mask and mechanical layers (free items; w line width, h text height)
Top Overlay:
  drawing of 20982 lines, arcs and shapes, not listed
  text "D8" at 4725,7045 h30
  text "D9" at 5015,7045 h30
  text "B5" at 7100,7020 h30
  text "INT" at 7300,7020 h30
  text "D10" at 4700,6955 h30
  text "D11" at 5015,6950 h30
  text "B13" at 7095,6930 h30
  text "B14" at 6790,6920 h30
  text "AD0" at 7295,6920 h30
  text "GND" at 4605,6880 h20
  text "3.3V" at 4295,6875 h20
  text "黑龙江科技大学" at 4180,6860 h120 r270
  text "D12" at 4700,6855 h30
  text "D13" at 5015,6855 h30
  text "XCL" at 7295,6830 h30
  text "B11" at 7100,6820 h30
  text "B12" at 6790,6815 h30
  text "SCL" at 4605,6785 h20
  text "WRST" at 4295,6780 h20
  text "D14" at 4700,6750 h30
  text "D15" at 5015,6750 h30
  text "B10" at 6790,6720 h30
  text "E15" at 7095,6720 h30
  text "XDL" at 7295,6720 h30
  text "VCC" at 7615,6695 h30
  text "RRST" at 4295,6680 h20
  text "SDA" at 4605,6680 h20
  text "G2" at 4715,6660 h30
  text "G3" at 5015,6650 h30
  text "万斌辉" at 4050,6645 h120 r270
  text "E14" at 6790,6625 h30
  text "E13" at 7095,6620 h30
  text "SDL" at 7295,6615 h30
  text "CSN" at 7615,6595 h30
  text "OE" at 4330,6585 h20
  text "D0" at 4605,6580 h20
  text "G5" at 5015,6555 h30
  text "G4" at 4720,6550 h30
  text "E11" at 7100,6530 h30
  text "E12" at 6790,6525 h30
  text "SCL" at 7290,6520 h30
  text "MOSI" at 7615,6490 h30
  text "D1" at 4335,6485 h20
  text "D2" at 4605,6480 h20
  text "G7" at 5015,6455 h30
  text "G6" at 4720,6450 h30
  text "E10" at 6790,6420 h30
  text "E9" at 7105,6420 h30
  text "GND" at 7290,6420 h30
  text "IRQ" at 7615,6390 h30
  text "D4" at 4330,6385 h20
  text "D3" at 4605,6380 h20
  text "G8" at 4720,6355 h30
  text "C6" at 5015,6355 h30
  text "E8" at 6815,6325 h30
  text "5V" at 7295,6320 h30
  text "E7" at 7105,6315 h30
  text "WIFE" at 7385,6297 h30
  text "D5" at 4330,6285 h20
  text "D6" at 4605,6280 h20
  text "C7" at 4720,6255 h30
  text "C8" at 5015,6250 h30
  text "6050" at 7179,6226 h30
  text "G1" at 6825,6225 h30
  text "G0" at 7105,6225 h30
  text "D7" at 4330,6185 h20
  text "RCLK" at 4605,6185 h20
  text "C9" at 4720,6155 h30
  text "A8" at 5015,6155 h30
  text "F15" at 6790,6125 h30
  text "F14" at 7100,6125 h30
  text "YSY" at 4315,6085 h20
  text "WEN" at 4605,6085 h20
  text "A9" at 4720,6055 h30
  text "A10" at 5015,6055 h30
  text "F13" at 6790,6025 h30
  text "F12" at 7095,6015 h30
  text "A12" at 5015,5955 h30
  text "A11" at 4705,5945 h30
  text "F11" at 6800,5925 h30
  text "B1" at 7095,5920 h30
  text "A14" at 5015,5855 h30
  text "A13" at 4695,5850 h30
  text "C5" at 7095,5830 h30
  text "B0" at 6815,5825 h30
  text "SDA" at 7295,5810 h30
  text "A15" at 4695,5755 h30
  text "C10" at 5015,5750 h30
  text "A7" at 7095,5730 h30
  text "C4" at 6815,5720 h30
  text "SCL" at 7295,5715 h30
  text "C12" at 5015,5655 h30
  text "C11" at 4705,5650 h30
  text "A6" at 6815,5625 h30
  text "A5" at 7095,5620 h30
  text "GND" at 7295,5615 h30
  text "D1" at 5015,5550 h30
  text "D0" at 4715,5530 h30
  text "A4" at 6815,5525 h30
  text "A3" at 7095,5515 h30
  text "3.3V" at 7295,5505 h30
  text "D3" at 5015,5455 h30
  text "D2" at 4720,5450 h30
  text "A1" at 7095,5425 h30
  text "A2" at 6815,5420 h30
  text "OLED" at 7180,5418 h30
  text "D4" at 4720,5350 h30
  text "D5" at 5015,5350 h30
  text "C3" at 7095,5330 h30
  text "A0" at 6815,5325 h30
  text "D6" at 4720,5250 h30
  text "D7" at 5015,5250 h30
  text "C1" at 7095,5230 h30
  text "C2" at 6815,5220 h30
  text "G10" at 5015,5155 h30
  text "G9" at 4720,5150 h30
  text "F10" at 7095,5130 h30
  text "C0" at 6815,5125 h30
  text "XHX" at 6213,5083 h360
  text "G12" at 5015,5055 h30
  text "G11" at 4710,5050 h30
  text "F8" at 7095,5025 h30
  text "F9" at 6815,5020 h30
  text "G14" at 5015,4955 h30
  text "G13" at 4705,4950 h30
  text "F7" at 6815,4920 h30
  text "F6" at 7095,4920 h30
  text "B3" at 5015,4855 h30
  text "G15" at 4705,4850 h30
  text "F5" at 6815,4820 h30
  text "F4" at 7095,4820 h30
  text "B4" at 4725,4755 h30
  text "B5" at 5015,4750 h30
  text "F3" at 6815,4725 h30
  text "F2" at 7095,4720 h30
  text "B6" at 4720,4655 h30
  text "B7" at 5015,4650 h30
  text "F1" at 6820,4625 h30
  text "F0" at 7095,4625 h30
  text "TXD" at 5389,4597 h30
  text "A10" at 5286,4594 h30
  text "B8" at 4720,4555 h30
  text "B9" at 5015,4550 h30
  text "E6" at 7095,4530 h30
  text "E7" at 6815,4525 h30
  text "E0" at 4720,4450 h30
  text "E1" at 5015,4450 h30
  text "E5" at 6815,4425 h30
  text "E4" at 7095,4425 h30
  text "5V" at 4720,4350 h30
  text "5V" at 5010,4350 h30
  text "A9" at 5293,4348 h30
  text "RXD" at 5387,4347 h30
  text "E3" at 6810,4320 h30
  text "E2" at 7095,4315 h30
  text "3.3V" at 4705,4255 h20
  text "3.3V" at 5015,4255 h20
  text "GND" at 6785,4220 h30
  text "GND" at 7095,4220 h30
  text "GND" at 4720,4155 h20
  text "GND" at 5015,4155 h20
  text "5V" at 7095,4120 h30
  text "5V" at 6810,4110 h30
  text "GND" at 5005,4005 h20
  text "3.3V" at 4710,3985 h20
  text "1" at 6714,3982 h30
  text "3.3V" at 4710,3910 h20
  text "GND" at 5005,3905 h20
  text "boot1" at 6715,3878 h30
  text "3.3V" at 4710,3810 h20
  text "GND" at 5005,3810 h20
  text "0" at 6713.08,3759.3 h30
  text "+5V" at 6874,3671 h30
  text "GND" at 7007,3663 h30
Bottom Solder:
  lines w7: 3977,3298 4062,3213 7740,3213 7740,7060 7705,7095 4057,7095 3977,7015 3977,3298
